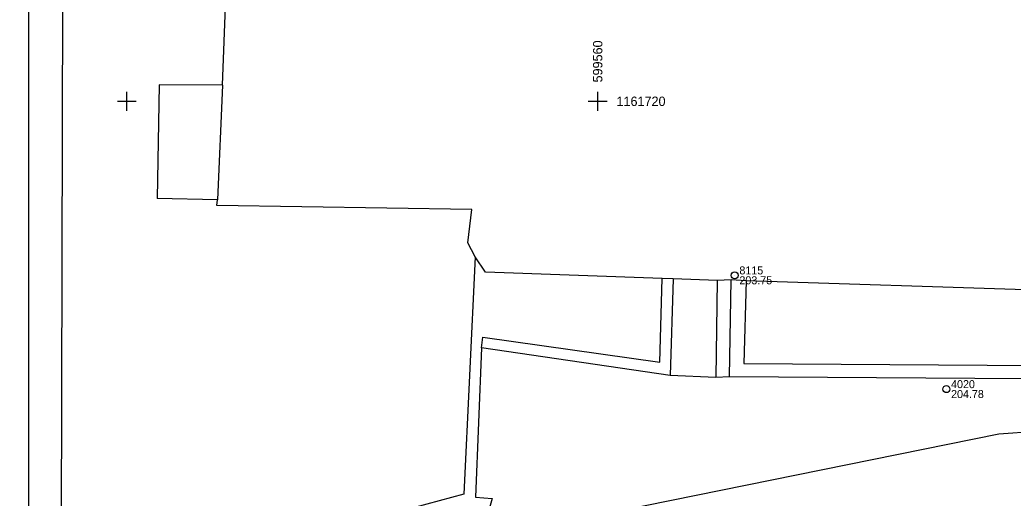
# Model space of a CAD drawing. Extents: x -599717 to -599336, y -1161826 to -1161587.
# Drawn here: x -599584.54 to -599542.35, y -1161736.85 to -1161716.54 of the extents above; entities that cross this region are included whole.
import ezdxf

# ---------------------------------------------------------------- set-up
doc = ezdxf.new("R2010")
doc.units = 0
for name, color, linetype in [('BODY_POLYGONY', 7, 'Continuous'), ('KN_Hranice parcel', 7, 'Continuous'), ('KN_Vnitřní kresba', 7, 'Continuous'), ('X_RAM_ROZPISKA', 7, 'Continuous'), ('X_SOUR_KRIZKY_SEVER', 7, 'Continuous')]:
    doc.layers.add(name, color=color, linetype=linetype)

msp = doc.modelspace()

# ---------------------------------------------------------------- linework, layer by layer
at = {"layer": 'BODY_POLYGONY'}
for centre, radius in [((-599554.18, -1161727.39), 0.15), ((-599554.18, -1161727.39), 0.0002), ((-599545.19, -1161732.22), 0.15), ((-599545.19, -1161732.22), 0.0002)]:
    msp.add_circle(centre, radius, dxfattribs=at)
at = {"layer": 'KN_Hranice parcel'}
for points in [[(-599584.54, -1161668.58), (-599584.29, -1161669.02), (-599582.61, -1161671.08), (-599582.79, -1161737.97), (-599582.79, -1161738.54)], [(-599490.94, -1161727.23), (-599493.9, -1161727.09), (-599494.94, -1161727.04), (-599495.2, -1161727.02), (-599495.72, -1161727), (-599495.93, -1161733.16), (-599523.16, -1161731.91), (-599554.4, -1161731.7), (-599554.98, -1161731.73), (-599556.92, -1161731.64), (-599564.93, -1161730.47), (-599565.19, -1161736.81), (-599564.48, -1161736.87), (-599564.6, -1161737.26), (-599565.68, -1161737.31), (-599572.63, -1161739.15), (-599582.79, -1161738.54)]]:
    msp.add_lwpolyline(points, dxfattribs=at)
at = {"layer": 'KN_Vnitřní kresba'}
for p, q in [((-599575.94, -1161719.31), (-599574.35, -1161679.01)), ((-599578.62, -1161719.3), (-599578.71, -1161724.12)), ((-599575.94, -1161719.31), (-599578.62, -1161719.3)), ((-599575.94, -1161719.31), (-599576.14, -1161724.19)), ((-599576.14, -1161724.19), (-599578.71, -1161724.12)), ((-599576.18, -1161724.42), (-599576.14, -1161724.19)), ((-599565.34, -1161724.59), (-599576.18, -1161724.42)), ((-599565.52, -1161726.01), (-599565.34, -1161724.59)), ((-599565.2, -1161726.61), (-599565.52, -1161726.01)), ((-599565.2, -1161726.61), (-599565.69, -1161736.68)), ((-599564.77, -1161727.25), (-599565.2, -1161726.61)), ((-599557.26, -1161727.53), (-599564.77, -1161727.25)), ((-599557.36, -1161731.08), (-599557.26, -1161727.53)), ((-599556.8, -1161727.54), (-599557.26, -1161727.53)), ((-599556.8, -1161727.54), (-599556.92, -1161731.64)), ((-599554.93, -1161727.61), (-599556.8, -1161727.54)), ((-599554.93, -1161727.61), (-599554.98, -1161731.73)), ((-599554.33, -1161727.58), (-599554.93, -1161727.61)), ((-599554.4, -1161731.7), (-599554.33, -1161727.58)), ((-599553.7, -1161727.63), (-599554.33, -1161727.58)), ((-599553.7, -1161727.63), (-599553.79, -1161731.13)), ((-599525.47, -1161728.52), (-599553.7, -1161727.63)), ((-599564.93, -1161730.47), (-599564.88, -1161730.01)), ((-599564.88, -1161730.01), (-599557.36, -1161731.08)), ((-599553.79, -1161731.13), (-599522.92, -1161731.36)), ((-599542.96, -1161734.12), (-599531.85, -1161733.35)), ((-599569.33, -1161739.45), (-599542.96, -1161734.12)), ((-599565.69, -1161736.68), (-599572.56, -1161738.53))]:
    msp.add_line(p, q, dxfattribs=at)
at = {"layer": 'X_RAM_ROZPISKA'}
msp.add_lwpolyline([(-599584.175, -1161747.535), (-599458.175, -1161747.535), (-599458.175, -1161628.735), (-599584.175, -1161628.735)], close=True, dxfattribs=at)
at = {"layer": 'X_SOUR_KRIZKY_SEVER'}
for p, q in [((-599580, -1161720.4), (-599580, -1161719.6)), ((-599560, -1161720.4), (-599560, -1161719.6)), ((-599580.4, -1161720), (-599579.6, -1161720)), ((-599560.4, -1161720), (-599559.6, -1161720))]:
    msp.add_line(p, q, dxfattribs=at)

# ---------------------------------------------------------------- texts
at = {"layer": 'BODY_POLYGONY'}
for s, p in [('8115', (-599553.98, -1161727.35)), ('203.75', (-599553.98, -1161727.77)), ('4020', (-599544.99, -1161732.18)), ('204.78', (-599544.99, -1161732.6))]:
    msp.add_text(s, height=0.34, dxfattribs=at).set_placement(p)
at = {"layer": 'X_SOUR_KRIZKY_SEVER'}
msp.add_text('599560', height=0.4, rotation=90, dxfattribs=at).set_placement((-599559.8, -1161719.2))
msp.add_text('1161720', height=0.4, dxfattribs=at).set_placement((-599559.2, -1161720.2))

doc.saveas('drawing.dxf')
